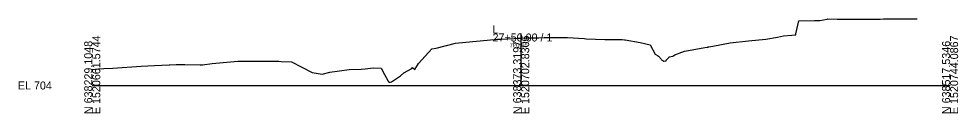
# Model space of a CAD drawing. Extents: x -26 to 3903, y -10 to 9531.
# Drawn here: x 974.3 to 1302.8, y 7490.3 to 7523.3 of the extents above; entities that cross this region are included whole.
import ezdxf

# ---------------------------------------------------------------- set-up
doc = ezdxf.new("R2010")
doc.units = 0
for name, color, linetype in [('Default', 7, 'Continuous'), ('Exist Cross Section Cell', 7, 'Continuous'), ('Exist XS Center Line Elevation Label', 7, 'Continuous'), ('Exist XS Ground Line', 7, 'Continuous')]:
    doc.layers.add(name, color=color, linetype=linetype)

msp = doc.modelspace()

# ---------------------------------------------------------------- linework, layer by layer
at = {"layer": 'Exist Cross Section Cell'}
for p, q in [((1150, 7500), (1150, 7518.19)), ((1000, 7500), (1150, 7500)), ((1150, 7500), (1300, 7500))]:
    msp.add_line(p, q, dxfattribs=at)
at = {"layer": 'Exist XS Ground Line'}
msp.add_lwpolyline([(1000, 7505.63), (1002.21, 7505.77), (1004, 7505.89), (1007.21, 7506.11), (1017.12, 7506.72), (1021.74, 7506.98), (1026.86, 7507.21), (1027.05, 7507.23), (1027.1, 7507.23), (1029.4, 7507.33), (1030.7, 7507.34), (1032.32, 7507.33), (1037.71, 7507.22), (1038.37, 7507.21), (1038.58, 7507.23), (1041.92, 7507.65), (1050.88, 7508.52), (1051.27, 7508.56), (1051.47, 7508.53), (1065.28, 7508.5), (1066.04, 7508.44), (1069.69, 7508.25), (1076.95, 7504.54), (1080.45, 7503.99), (1083.11, 7504.71), (1089.86, 7505.6), (1094.01, 7505.69), (1095.42, 7505.87), (1098.2, 7506.21), (1101.09, 7506.08), (1102.15, 7503.9), (1103.54, 7501.47), (1103.84, 7501.06), (1104.63, 7501.23), (1107.75, 7503.43), (1108.94, 7504.47), (1111.77, 7505.96), (1112.05, 7506.28), (1112.76, 7505.55), (1114.08, 7507.67), (1118.71, 7512.76), (1120.27, 7513), (1127.05, 7514.76), (1128.16, 7514.87), (1140.6, 7516.05), (1141.21, 7516.11), (1141.76, 7516.18), (1142.18, 7516.2), (1142.75, 7516.23), (1142.91, 7516.25), (1144.94, 7516.34), (1144.97, 7516.34), (1145.02, 7516.34), (1147.57, 7516.46), (1148.98, 7516.51), (1150.16, 7516.56), (1151.8, 7516.62), (1152.27, 7516.64), (1152.46, 7516.64), (1152.65, 7516.65), (1153.7, 7516.68), (1153.97, 7516.7), (1155.81, 7516.72), (1156.14, 7516.72), (1158.01, 7516.75), (1158.74, 7516.76), (1160.04, 7516.78), (1161.35, 7516.79), (1162.07, 7516.79), (1163.94, 7516.8), (1164.05, 7516.8), (1166, 7516.79), (1166.22, 7516.8), (1172.07, 7516.4), (1172.68, 7516.37), (1179.28, 7516.06), (1185.36, 7516.03), (1186.11, 7516.02), (1186.41, 7515.98), (1191.65, 7515.09), (1195.12, 7514.25), (1196.87, 7510.98), (1197.73, 7510.43), (1197.99, 7510.25), (1199.11, 7509.06), (1199.22, 7508.87), (1199.4, 7508.71), (1199.5, 7508.69), (1199.91, 7508.56), (1200.53, 7508.61), (1200.69, 7508.64), (1200.73, 7508.85), (1200.96, 7509.05), (1201.77, 7509.87), (1201.79, 7510.06), (1202.98, 7510.28), (1203.77, 7510.74), (1207.09, 7512.04), (1208.57, 7512.21), (1214.26, 7513.25), (1215.02, 7513.37), (1215.19, 7513.42), (1215.22, 7513.42), (1215.36, 7513.46), (1215.61, 7513.5), (1216.98, 7513.76), (1223.07, 7514.93), (1229.52, 7515.63), (1235.53, 7516.15), (1239.61, 7516.9), (1241.7, 7517.34), (1244.71, 7517.59), (1245.87, 7517.68), (1246.03, 7517.67), (1246.07, 7518.01), (1247.07, 7522.61), (1252.61, 7522.73), (1254.47, 7522.78), (1257.05, 7523.22), (1257.3, 7523.26), (1260.5, 7523.17), (1275.6, 7523.23), (1276.7, 7523.25), (1288.07, 7523.31), (1288.31, 7523.32), (1288.37, 7523.32), (1288.54, 7523.31)], dxfattribs=at)

# ---------------------------------------------------------------- texts
at = {"layer": 'Default'}
msp.add_text('-', height=0.0001, dxfattribs=at).set_placement((1000, 7500))
at = {"layer": 'Exist Cross Section Cell'}
for s, p in [('L', (1140, 7518.19)), ('27+50.00 / 1', (1140, 7515.39)), ('EL 704', (974, 7498.6))]:
    msp.add_text(s, height=2.8, dxfattribs=at).set_placement(p)
for s, p in [('E 1520661.5744', (1002.8, 7490)), ('E 1520702.8306', (1152.8, 7490)), ('E 1520744.0867', (1302.8, 7490)), ('N 638229.1048', (1000, 7490)), ('N 638373.3197', (1150, 7490)), ('N 638517.5346', (1300, 7490))]:
    msp.add_text(s, height=2.8, rotation=90, dxfattribs=at).set_placement(p)
at = {"layer": 'Exist XS Center Line Elevation Label'}
msp.add_text('720.55', height=1.5, rotation=0.8401, dxfattribs=at).set_placement((1145.97, 7513.28))

doc.saveas('drawing.dxf')
